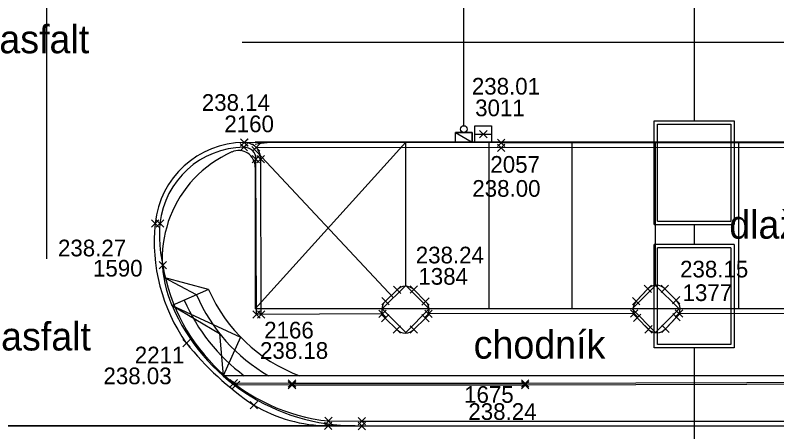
# Model space of a CAD drawing. Extents: x -264165 to -263733, y -1242319 to -1242245.
# Drawn here: x -263924.28 to -263901.43, y -1242301.66 to -1242289.18 of the extents above; entities that cross this region are included whole.
import ezdxf

# ---------------------------------------------------------------- set-up
doc = ezdxf.new("R2010")
doc.units = 0
for name, color, linetype in [('KFA_BOD_CISLO', 7, 'Continuous'), ('KFA_BOD_SYMBOL', 7, 'Continuous'), ('KFA_BOD_VYSKA', 7, 'Continuous'), ('KFA_SO_20-2_OBRUBNIKY_DOLNA_HRANA', 7, 'Continuous'), ('KFA_SO_20-2_OBRUBNIKY_HORNA_HRANA', 7, 'Continuous'), ('KFA_UV_BOD_CISLO', 7, 'Continuous'), ('KFA_UV_BOD_SYMBOL', 7, 'Continuous'), ('KFA_UV_BOD_VYSKA', 7, 'Continuous'), ('POPIS', 7, 'Continuous'), ('PROJEKT_OBRUBNIKY_KOMUNIKACIE', 7, 'Continuous'), ('PROJEKT_TDZ_VODOROVNE', 7, 'Continuous'), ('ROZHRANIE_SO_20-1_a_20-2', 7, 'Continuous'), ('SITUACIA_DSP_2D', 7, 'Continuous'), ('SO_20-1_OBRUBNIKY_DOLNA_HRANA', 7, 'Continuous'), ('SO_20-1_OBRUBNIKY_HORNA_HRANA', 7, 'Continuous'), ('ULICNA_VPUST_POKLOP', 7, 'Continuous')]:
    doc.layers.add(name, color=color, linetype=linetype)

msp = doc.modelspace()

# ---------------------------------------------------------------- linework, layer by layer
at = {"layer": 'KFA_BOD_SYMBOL'}
for p, q in [((-263917.524, -1242293.106), (-263917.303, -1242292.884)), ((-263917.303, -1242293.106), (-263917.524, -1242292.884)), ((-263917.52, -1242293.107), (-263917.299, -1242292.887)), ((-263917.299, -1242293.107), (-263917.52, -1242292.887)), ((-263909.816, -1242293.113), (-263909.595, -1242292.893)), ((-263909.595, -1242293.113), (-263909.816, -1242292.893)), ((-263917.533, -1242293.249), (-263917.312, -1242293.029)), ((-263917.312, -1242293.249), (-263917.533, -1242293.029)), ((-263917.167, -1242293.254), (-263916.946, -1242293.032)), ((-263916.946, -1242293.254), (-263917.167, -1242293.032)), ((-263909.817, -1242293.262), (-263909.595, -1242293.041)), ((-263909.595, -1242293.262), (-263909.817, -1242293.041)), ((-263917.171, -1242293.606), (-263916.95, -1242293.384)), ((-263916.95, -1242293.606), (-263917.171, -1242293.384)), ((-263917.029, -1242293.603), (-263916.807, -1242293.383)), ((-263916.807, -1242293.603), (-263917.029, -1242293.383)), ((-263920.197, -1242295.529), (-263919.976, -1242295.308)), ((-263919.976, -1242295.529), (-263920.197, -1242295.308)), ((-263920.051, -1242295.535), (-263919.829, -1242295.313)), ((-263919.829, -1242295.535), (-263920.051, -1242295.313)), ((-263919.965, -1242296.784), (-263919.744, -1242296.562)), ((-263919.744, -1242296.784), (-263919.965, -1242296.562)), ((-263912.938, -1242297.522), (-263912.717, -1242297.302)), ((-263912.717, -1242297.522), (-263912.938, -1242297.302)), ((-263912.437, -1242297.512), (-263912.215, -1242297.291)), ((-263912.215, -1242297.512), (-263912.437, -1242297.291)), ((-263905.41, -1242297.488), (-263905.188, -1242297.268)), ((-263905.188, -1242297.488), (-263905.41, -1242297.268)), ((-263904.905, -1242297.487), (-263904.683, -1242297.265)), ((-263904.683, -1242297.487), (-263904.905, -1242297.265)), ((-263913.283, -1242297.86), (-263913.062, -1242297.639)), ((-263913.062, -1242297.86), (-263913.283, -1242297.639)), ((-263912.082, -1242297.866), (-263911.861, -1242297.644)), ((-263911.861, -1242297.866), (-263912.082, -1242297.644)), ((-263905.761, -1242297.857), (-263905.54, -1242297.637)), ((-263905.54, -1242297.857), (-263905.761, -1242297.637)), ((-263904.561, -1242297.833), (-263904.34, -1242297.612)), ((-263904.34, -1242297.833), (-263904.561, -1242297.612)), ((-263917.15, -1242298.255), (-263916.929, -1242298.035)), ((-263916.929, -1242298.255), (-263917.15, -1242298.035)), ((-263917.011, -1242298.255), (-263916.79, -1242298.034)), ((-263916.79, -1242298.255), (-263917.011, -1242298.034)), ((-263913.376, -1242298.238), (-263913.155, -1242298.018)), ((-263913.155, -1242298.238), (-263913.376, -1242298.018)), ((-263913.291, -1242298.367), (-263913.07, -1242298.147)), ((-263913.07, -1242298.367), (-263913.291, -1242298.147)), ((-263912.084, -1242298.367), (-263911.863, -1242298.146)), ((-263911.863, -1242298.367), (-263912.084, -1242298.146)), ((-263911.998, -1242298.241), (-263911.777, -1242298.019)), ((-263911.777, -1242298.241), (-263911.998, -1242298.019)), ((-263905.826, -1242298.232), (-263905.605, -1242298.012)), ((-263905.605, -1242298.232), (-263905.826, -1242298.012)), ((-263905.735, -1242298.363), (-263905.514, -1242298.141)), ((-263905.514, -1242298.363), (-263905.735, -1242298.141)), ((-263904.551, -1242298.34), (-263904.329, -1242298.119)), ((-263904.329, -1242298.34), (-263904.551, -1242298.119)), ((-263904.478, -1242298.232), (-263904.257, -1242298.012)), ((-263904.257, -1242298.232), (-263904.478, -1242298.012)), ((-263912.948, -1242298.707), (-263912.726, -1242298.485)), ((-263912.726, -1242298.707), (-263912.948, -1242298.485)), ((-263912.432, -1242298.704), (-263912.212, -1242298.484)), ((-263912.212, -1242298.704), (-263912.432, -1242298.484)), ((-263905.394, -1242298.704), (-263905.174, -1242298.482)), ((-263905.174, -1242298.704), (-263905.394, -1242298.482)), ((-263904.887, -1242298.691), (-263904.666, -1242298.471)), ((-263904.666, -1242298.691), (-263904.887, -1242298.471)), ((-263919.259, -1242299.113), (-263919.038, -1242298.893)), ((-263919.038, -1242299.113), (-263919.259, -1242298.893)), ((-263917.832, -1242300.318), (-263917.611, -1242300.096)), ((-263917.611, -1242300.318), (-263917.832, -1242300.096)), ((-263917.764, -1242300.367), (-263917.543, -1242300.147)), ((-263917.543, -1242300.367), (-263917.764, -1242300.147)), ((-263916.089, -1242300.33), (-263915.867, -1242300.11)), ((-263915.867, -1242300.33), (-263916.089, -1242300.11)), ((-263916.089, -1242300.38), (-263915.867, -1242300.16)), ((-263915.867, -1242300.38), (-263916.089, -1242300.16)), ((-263909.098, -1242300.323), (-263908.877, -1242300.102)), ((-263908.877, -1242300.323), (-263909.098, -1242300.102)), ((-263909.098, -1242300.373), (-263908.877, -1242300.151)), ((-263908.877, -1242300.373), (-263909.098, -1242300.151)), ((-263917.237, -1242300.971), (-263917.016, -1242300.751)), ((-263917.016, -1242300.971), (-263917.237, -1242300.751)), ((-263914.991, -1242301.45), (-263914.769, -1242301.228)), ((-263914.769, -1242301.45), (-263914.991, -1242301.228)), ((-263913.995, -1242301.454), (-263913.774, -1242301.234)), ((-263913.774, -1242301.454), (-263913.995, -1242301.234)), ((-263915, -1242301.593), (-263914.779, -1242301.372)), ((-263914.779, -1242301.593), (-263915, -1242301.372)), ((-263913.995, -1242301.6), (-263913.774, -1242301.379)), ((-263913.774, -1242301.6), (-263913.995, -1242301.379))]:
    msp.add_line(p, q, dxfattribs=at)
at = {"layer": 'KFA_SO_20-2_OBRUBNIKY_DOLNA_HRANA'}
msp.add_line((-263914.889, -1242301.482), (-263913.884, -1242301.489), dxfattribs=at)
for points in [[(-263817.492, -1242292.982), (-263829.632, -1242292.973), (-263839.651, -1242292.963), (-263849.653, -1242292.97), (-263858.67, -1242292.978), (-263866.671, -1242292.969), (-263877.683, -1242292.971), (-263887.693, -1242292.984), (-263898.705, -1242293.002), (-263909.705, -1242293.003), (-263917.41, -1242292.997)], [(-263817.431, -1242293.129), (-263829.63, -1242293.121), (-263839.649, -1242293.107), (-263849.656, -1242293.117), (-263858.667, -1242293.124), (-263866.668, -1242293.115), (-263877.682, -1242293.116), (-263887.695, -1242293.128), (-263898.705, -1242293.142), (-263909.706, -1242293.151), (-263917.057, -1242293.143)], [(-263916.9, -1242298.144), (-263916.918, -1242293.493)]]:
    msp.add_lwpolyline(points, dxfattribs=at)
for centre, major_axis, ratio, start_param, end_param in [((-263917.405, -1242295.69), (-2.474, 1.068), 0.999988, 5.123489, 6.589707), ((-263917.409, -1242293.486), (-0.149, 0.468), 0.999518, 4.390715, 5.986008), ((-263914.827, -1242295.95), (-1.976, -4.912), 0.998297, 4.993638, 5.709075), ((-263913.261, -1242294.538), (5.791, -5.726), 0.905695, 4.583348, 4.922188), ((-263914.949, -1242297.237), (3.926, -1.825), 0.97645, 4.608946, 5.152477)]:
    msp.add_ellipse(centre, major_axis=major_axis, ratio=ratio, start_param=start_param, end_param=end_param, dxfattribs=at)
at = {"layer": 'KFA_SO_20-2_OBRUBNIKY_HORNA_HRANA'}
for p, q in [((-263917.04, -1242298.145), (-263917.061, -1242293.495)), ((-263913.172, -1242297.749), (-263912.828, -1242297.412)), ((-263912.326, -1242297.401), (-263911.971, -1242297.755)), ((-263905.65, -1242297.747), (-263905.299, -1242297.378)), ((-263904.794, -1242297.376), (-263904.45, -1242297.722)), ((-263913.265, -1242298.128), (-263917.04, -1242298.145)), ((-263905.715, -1242298.122), (-263911.888, -1242298.13)), ((-263898.287, -1242298.126), (-263904.367, -1242298.122)), ((-263912.837, -1242298.596), (-263913.181, -1242298.257)), ((-263912.322, -1242298.594), (-263911.974, -1242298.256)), ((-263905.284, -1242298.593), (-263905.624, -1242298.252)), ((-263904.776, -1242298.581), (-263904.44, -1242298.229)), ((-263914.88, -1242301.339), (-263913.884, -1242301.344))]:
    msp.add_line(p, q, dxfattribs=at)
for points in [[(-263818.454, -1242300.127), (-263820.114, -1242300.153), (-263830.062, -1242300.171), (-263840.06, -1242300.171), (-263850.054, -1242300.16), (-263860.027, -1242300.174), (-263870.031, -1242300.18), (-263880.008, -1242300.187), (-263888.684, -1242300.195), (-263899.013, -1242300.19), (-263908.987, -1242300.212), (-263915.978, -1242300.22), (-263917.721, -1242300.207)], [(-263818.504, -1242300.177), (-263820.112, -1242300.193), (-263830.062, -1242300.221), (-263840.06, -1242300.221), (-263850.054, -1242300.21), (-263860.027, -1242300.224), (-263870.031, -1242300.23), (-263880.008, -1242300.237), (-263888.684, -1242300.245), (-263899.013, -1242300.24), (-263908.987, -1242300.262), (-263915.978, -1242300.27), (-263917.654, -1242300.257)]]:
    msp.add_lwpolyline(points, dxfattribs=at)
for centre, major_axis, ratio, start_param, end_param in [((-263917.404, -1242293.482), (-0.033, 0.341), 0.999429, 4.577762, 6.241525), ((-263917.395, -1242295.698), (-0.504, 2.509), 0.999998, 6.095491, 7.548578), ((-263915.648, -1242295.758), (0.189, -4.341), 0.990733, 4.592186, 4.881319), ((-263914.291, -1242295.732), (-5.387, 1.689), 0.998644, 0.471936, 1.769635), ((-263912.572, -1242297.653), (-0.345, 0.066), 0.999817, 4.126885, 5.717581), ((-263905.046, -1242297.617), (-0.339, -0.084), 0.999119, 3.664284, 5.284192), ((-263912.938, -1242298.007), (-0.104, -0.333), 0.999611, 4.182568, 5.814295), ((-263912.209, -1242298.004), (0.023, 0.344), 0.99948, 3.959717, 5.588886), ((-263905.384, -1242297.986), (-0.03, -0.356), 0.999893, 4.063009, 5.632892), ((-263904.688, -1242297.98), (-0.07, 0.345), 0.999453, 3.726979, 5.338144), ((-263912.58, -1242298.349), (0.348, 0.078), 0.99855, 3.687392, 5.301187), ((-263905.036, -1242298.347), (0.335, -0.101), 0.999919, 4.214556, 5.840419)]:
    msp.add_ellipse(centre, major_axis=major_axis, ratio=ratio, start_param=start_param, end_param=end_param, dxfattribs=at)
at = {"layer": 'KFA_UV_BOD_SYMBOL'}
for p, q in [((-263910.35, -1242292.856), (-263910.128, -1242292.634)), ((-263910.128, -1242292.856), (-263910.35, -1242292.634))]:
    msp.add_line(p, q, dxfattribs=at)
at = {"layer": 'PROJEKT_OBRUBNIKY_KOMUNIKACIE'}
for p, q in [((-263817.19, -1242292.982), (-263917.08, -1242292.982)), ((-263917.08, -1242293.737), (-263917.08, -1242297.982)), ((-263918.48, -1242297.402), (-263919.828, -1242297.035)), ((-263918.48, -1242297.402), (-263919.579, -1242297.882)), ((-263815.601, -1242297.982), (-263917.08, -1242297.982)), ((-263816.308, -1242299.982), (-263918.049, -1242299.982)), ((-263914.08, -1242301.482), (-263815.822, -1242301.482))]:
    msp.add_line(p, q, dxfattribs=at)
for points in [[(-263912.568, -1242297.275), (-263911.861, -1242297.982), (-263912.568, -1242298.689), (-263913.275, -1242297.982), (-263912.568, -1242297.275)], [(-263905.068, -1242297.275), (-263904.361, -1242297.982), (-263905.068, -1242298.689), (-263905.775, -1242297.982), (-263905.068, -1242297.275)], [(-263919.579, -1242297.882), (-263917.521, -1242298.829), (-263918.049, -1242299.982)]]:
    msp.add_lwpolyline(points, dxfattribs=at)
for centre, radius, start, end in [((-263916.372, -1242296.482), 3.5, 113.7599, 203.5782), ((-263917.58, -1242293.737), 0.5, 0, 113.7599), ((-263914.08, -1242295.482), 4.8, 203.5782, 249.6359), ((-263914.08, -1242295.482), 6, 203.5782, 270), ((-263914.08, -1242295.482), 5.6, 203.5782, 233.4725)]:
    msp.add_arc(centre, radius, start, end, dxfattribs=at)
at = {"layer": 'PROJEKT_TDZ_VODOROVNE'}
for p, q in [((-263923.33, -1242296.482), (-263923.33, -1242254.982)), ((-263819.531, -1242289.994), (-263917.477, -1242289.994)), ((-263917.187, -1242293.118), (-263912.937, -1242297.644)), ((-263917.08, -1242297.982), (-263912.568, -1242292.982)), ((-263912.568, -1242297.275), (-263912.568, -1242292.982)), ((-263910.068, -1242297.982), (-263910.068, -1242292.982)), ((-263907.568, -1242297.982), (-263907.568, -1242292.982)), ((-263905.068, -1242297.275), (-263905.068, -1242292.982)), ((-263902.568, -1242297.982), (-263902.568, -1242292.982)), ((-263914.08, -1242301.482), (-263932.58, -1242301.482))]:
    msp.add_line(p, q, dxfattribs=at)
msp.add_arc((-263916.372, -1242296.482), 3.5, 90, 101.6826, dxfattribs=at)
at = {"layer": 'ROZHRANIE_SO_20-1_a_20-2'}
msp.add_line((-263931.888, -1242301.474), (-263913.884, -1242301.489), dxfattribs=at)
at = {"layer": 'SITUACIA_DSP_2D'}
for p, q in [((-263910.824, -1242292.492), (-263910.824, -1242284.343)), ((-263903.913, -1242284.482), (-263903.913, -1242292.347)), ((-263905.113, -1242292.347), (-263902.713, -1242292.347)), ((-263905.113, -1242295.447), (-263905.113, -1242292.347)), ((-263905.013, -1242292.447), (-263902.813, -1242292.447)), ((-263905.013, -1242295.347), (-263905.013, -1242292.447)), ((-263902.813, -1242292.447), (-263902.813, -1242295.347)), ((-263902.713, -1242292.347), (-263902.713, -1242295.447)), ((-263911.074, -1242292.692), (-263910.574, -1242292.692)), ((-263911.074, -1242292.982), (-263911.074, -1242292.692)), ((-263911.074, -1242292.692), (-263910.574, -1242292.982)), ((-263911.074, -1242292.692), (-263910.574, -1242292.982)), ((-263910.574, -1242292.692), (-263911.074, -1242292.692)), ((-263910.574, -1242292.692), (-263910.574, -1242292.982)), ((-263910.574, -1242292.982), (-263910.574, -1242292.692)), ((-263910.574, -1242292.982), (-263911.074, -1242292.982)), ((-263917.08, -1242293.737), (-263917.08, -1242297.982)), ((-263905.013, -1242295.347), (-263902.813, -1242295.347)), ((-263905.113, -1242295.447), (-263902.713, -1242295.447)), ((-263903.913, -1242295.447), (-263903.913, -1242296.047)), ((-263905.113, -1242299.147), (-263905.113, -1242296.047)), ((-263902.713, -1242296.047), (-263905.113, -1242296.047)), ((-263902.713, -1242296.047), (-263902.713, -1242299.147)), ((-263902.813, -1242296.147), (-263905.013, -1242296.147)), ((-263905.013, -1242299.047), (-263905.013, -1242296.147)), ((-263902.813, -1242296.147), (-263902.813, -1242299.047)), ((-263918.846, -1242297.562), (-263919.828, -1242297.035)), ((-263918.846, -1242297.562), (-263919.579, -1242297.882)), ((-263815.601, -1242297.982), (-263917.08, -1242297.982)), ((-263902.813, -1242299.047), (-263905.013, -1242299.047)), ((-263902.713, -1242299.147), (-263905.113, -1242299.147)), ((-263903.913, -1242299.147), (-263903.913, -1242303.647)), ((-263816.308, -1242299.982), (-263918.049, -1242299.982)), ((-263914.08, -1242301.482), (-263815.822, -1242301.482))]:
    msp.add_line(p, q, dxfattribs=at)
for points in [[(-263912.568, -1242297.275), (-263911.861, -1242297.982), (-263912.568, -1242298.689), (-263913.275, -1242297.982)], [(-263905.068, -1242297.275), (-263904.361, -1242297.982), (-263905.068, -1242298.689), (-263905.775, -1242297.982)]]:
    msp.add_lwpolyline(points, close=True, dxfattribs=at)
msp.add_lwpolyline([(-263919.579, -1242297.882), (-263918.155, -1242298.713), (-263918.049, -1242299.982)], dxfattribs=at)
msp.add_circle((-263910.824, -1242292.592), 0.1, dxfattribs=at)
for centre, radius, start, end in [((-263916.372, -1242296.482), 3.5, 113.7599, 203.5782), ((-263917.58, -1242293.737), 0.5, 0, 113.7599), ((-263914.08, -1242295.482), 5.2, 203.5782, 239.9267), ((-263914.08, -1242295.482), 6, 203.5782, 270), ((-263914.08, -1242295.482), 5.6, 203.5782, 233.4725)]:
    msp.add_arc(centre, radius, start, end, dxfattribs=at)
at = {"layer": 'SO_20-1_OBRUBNIKY_DOLNA_HRANA'}
msp.add_lwpolyline([(-263913.884, -1242301.489), (-263907.893, -1242301.489), (-263900.89, -1242301.488), (-263893.898, -1242301.483), (-263886.917, -1242301.473), (-263879.922, -1242301.465), (-263872.91, -1242301.469), (-263865.929, -1242301.465), (-263859.932, -1242301.473), (-263850.941, -1242301.471), (-263843.947, -1242301.471), (-263836.942, -1242301.481), (-263829.943, -1242301.484), (-263823.945, -1242301.487), (-263818.452, -1242301.495), (-263816.42, -1242301.504)], dxfattribs=at)
at = {"layer": 'SO_20-1_OBRUBNIKY_HORNA_HRANA'}
msp.add_lwpolyline([(-263913.884, -1242301.344), (-263907.893, -1242301.343), (-263900.896, -1242301.344), (-263893.895, -1242301.338), (-263886.916, -1242301.328), (-263879.921, -1242301.324), (-263872.911, -1242301.324), (-263865.928, -1242301.325), (-263859.931, -1242301.327), (-263850.935, -1242301.324), (-263843.941, -1242301.331), (-263836.939, -1242301.332), (-263829.941, -1242301.342), (-263823.94, -1242301.343), (-263818.456, -1242301.352), (-263816.413, -1242301.358)], dxfattribs=at)
at = {"layer": 'ULICNA_VPUST_POKLOP'}
msp.add_line((-263910.239, -1242292.745), (-263910.239, -1242292.745), dxfattribs=at)
msp.add_lwpolyline([(-263910.489, -1242292.745), (-263910.489, -1242292.495), (-263909.989, -1242292.495), (-263909.989, -1242292.995), (-263910.489, -1242292.995), (-263910.489, -1242292.745), (-263909.989, -1242292.745)], dxfattribs=at)

# ---------------------------------------------------------------- texts
at = {"layer": 'KFA_BOD_CISLO'}
for s, p in [('2160', (-263918.008, -1242292.686)), ('2057', (-263910.027, -1242293.9)), ('1590', (-263921.949, -1242297.012)), ('1384', (-263912.187, -1242297.256)), ('1377', (-263904.261, -1242297.744)), ('2166', (-263916.813, -1242298.867)), ('2211', (-263920.695, -1242299.613)), ('1675', (-263910.815, -1242300.795))]:
    msp.add_text(s, height=0.5, dxfattribs=at).set_placement(p)
at = {"layer": 'KFA_BOD_VYSKA'}
for s, p in [('238.14', (-263918.685, -1242292.047)), ('238.00', (-263910.568, -1242294.62)), ('238.27', (-263923, -1242296.406)), ('238.24', (-263912.265, -1242296.617)), ('238.15', (-263904.335, -1242297.038)), ('238.18', (-263916.938, -1242299.477)), ('238.03', (-263921.636, -1242300.238)), ('238.24', (-263910.687, -1242301.307))]:
    msp.add_text(s, height=0.5, dxfattribs=at).set_placement(p)
at = {"layer": 'KFA_UV_BOD_CISLO'}
msp.add_text('3011', height=0.5, dxfattribs=at).set_placement((-263910.483, -1242292.207))
at = {"layer": 'KFA_UV_BOD_VYSKA'}
msp.add_text('238.01', height=0.5, dxfattribs=at).set_placement((-263910.582, -1242291.559))
at = {"layer": 'POPIS'}
for s, p in [('asfalt', (-263924.76, -1242290.32)), ('dlažba', (-263902.86, -1242295.876)), ('asfalt', (-263924.707, -1242299.226)), ('chodník', (-263910.528, -1242299.471))]:
    msp.add_text(s, height=0.8438, dxfattribs=at).set_placement(p)

doc.saveas('drawing.dxf')
